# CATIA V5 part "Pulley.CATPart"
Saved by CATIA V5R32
Part number: Pulley
Bounding box of the stored display mesh (mm): x -40.838 to 40.838, y -33 to 33, z -40.838 to 40.838
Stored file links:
  D:\PROJECTS\Project 2022\CATIA V5 6R 2022\Resources\Part Files\c14_catia_v5_6r2022_prt\c14-catia-v5-6r2022-figr-14-26 & 27\Part & Asm\Pulley.CATPart
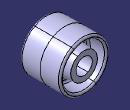
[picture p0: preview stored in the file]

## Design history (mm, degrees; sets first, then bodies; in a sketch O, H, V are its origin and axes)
Body1 (main body)
  Sketch1 on yz-plane, origin (0, 0, 0), H (0, 1, 0), V (0, 0, 1)
    line L1 (0, 13.45) -> (31.5, 13.45)
    point P1 (0, 13.45)
    point P2 (31.5, 13.45)
    line L2 (31.5, 13.45) -> (31.5, 22)
    point P3 (31.5, 22)
    line L3 (31.5, 22) -> (6, 24)
    point P4 (6, 24)
    line L4 (6, 24) -> (6, 33)
    point P5 (6, 33)
    line L5 (6, 33) -> (33, 35)
    point P6 (33, 35)
    line L6 (33, 35) -> (33, 41)
    point P7 (33, 41)
    line L7 (33, 41) -> (0, 41)
    point P8 (0, 41)
    point P9 (0, 41)
    point P10 (-33, 41)
    line L8 (-33, 41) -> (0, 41)
    point P11 (-33, 35)
    line L9 (-33, 35) -> (-33, 41)
    point P12 (-6, 33)
    line L10 (-6, 33) -> (-33, 35)
    point P13 (-6, 24)
    line L11 (-6, 24) -> (-6, 33)
    point P14 (-31.5, 22)
    line L12 (-31.5, 22) -> (-6, 24)
    point P15 (-31.5, 13.45)
    line L13 (-31.5, 13.45) -> (-31.5, 22)
    point P16 (0, 13.45)
    line L14 (0, 13.45) -> (-31.5, 13.45)
    length L1 = 31.5
    distance L1 H = 13.45
    distance P4 H = 24
    distance P3 H = 22
    distance L4 V = 6
    distance P5 H = 33
    distance P6 H = 35
    distance V L6 = 33
    distance L7 H = 41
    coincidence: P1 V, P8 V, P1 P16, P8 P9
    horizontal: L1 H, L7 H
    vertical: L2 V, L4 V, L6 V
    symmetry: P8 P9 V, P7 P10 V, L7 L8 V, P6 P11 V, L6 L9 V, P5 P12 V, L5 L10 V, P4 P13 V, L4 L11 V, P3 P14 V, L3 L12 V, P2 P15 V, L2 L13 V, P1 P16 V, L1 L14 V
  Shaft1: profile Sketch1, axis Sketch1.H, angle 360
  Fillet1: radius 3, on 4 faces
